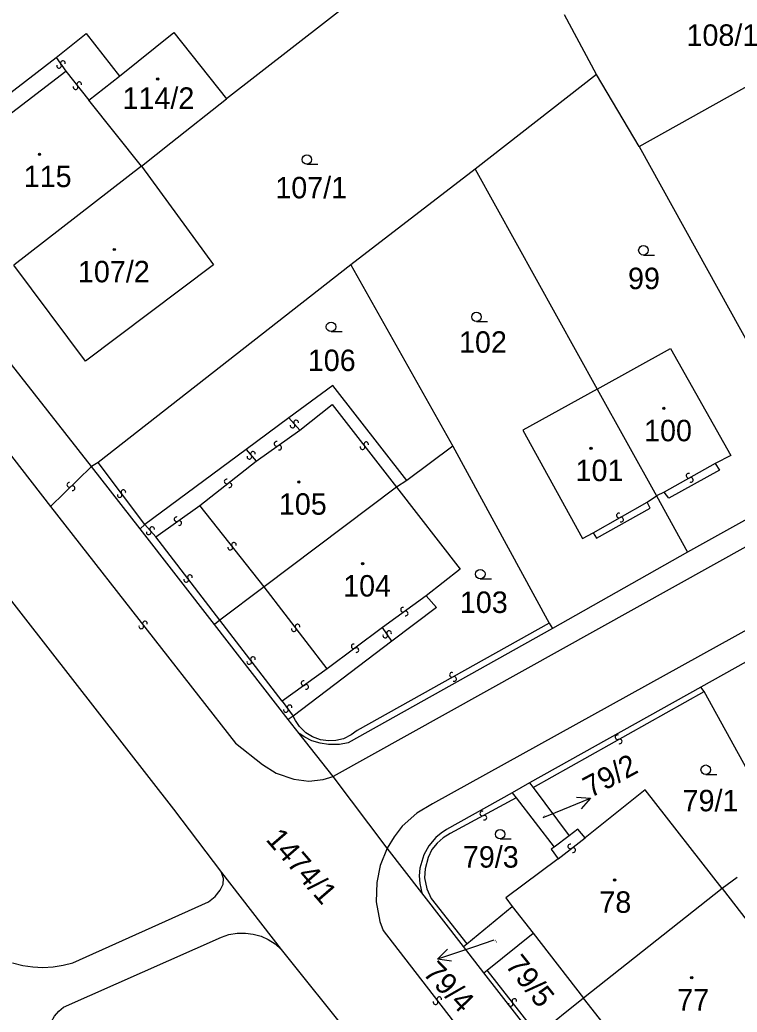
# Model space of a CAD drawing. Extents: x -600391 to -599491, y -1160176 to -1159402.
# Drawn here: x -600331.1 to -600274.3, y -1159991 to -1159912.4 of the extents above; entities that cross this region are included whole.
import ezdxf

# ---------------------------------------------------------------- set-up
doc = ezdxf.new("R2010")
doc.units = 0
for name, color, linetype in [('Level 1', 7, 'Continuous'), ('Level 13', 7, 'Continuous'), ('Level 3', 7, 'Continuous'), ('Level 4', 7, 'Continuous'), ('Level 5', 7, 'Continuous'), ('Level 57', 7, 'Continuous')]:
    doc.layers.add(name, color=color, linetype=linetype)

msp = doc.modelspace()

# ---------------------------------------------------------------- linework, layer by layer
at = {"layer": 'Level 1'}
for points in [[(-600376.7, -1159900.77), (-600365.93, -1159914.53), (-600350.97, -1159933.8), (-600318.93, -1159974.9), (-600315.13, -1159979.92)], [(-600293.45, -1159902.08), (-600314.74, -1159918.62)], [(-600285.41, -1159916.7), (-600287.96, -1159911.98)], [(-600328.23, -1159915.36), (-600325.84, -1159913.45), (-600323.21, -1159916.82)], [(-600323.21, -1159916.82), (-600318.91, -1159913.37), (-600314.74, -1159918.62)], [(-600282.04, -1159922.4), (-600265.99, -1159913.45)], [(-600341.92, -1159925.88), (-600328.23, -1159915.36)], [(-600325.64, -1159918.73), (-600323.21, -1159916.82)], [(-600285.41, -1159916.7), (-600295.04, -1159924.21)], [(-600282.04, -1159922.4), (-600285.41, -1159916.7)], [(-600321.47, -1159923.97), (-600319.15, -1159922.12), (-600314.74, -1159918.62)], [(-600321.47, -1159923.97), (-600325.64, -1159918.73)], [(-600282.04, -1159922.4), (-600267.75, -1159948.2)], [(-600321.47, -1159923.97), (-600331.59, -1159931.8)], [(-600321.47, -1159923.97), (-600315.76, -1159931.77), (-600325.9, -1159939.4), (-600331.59, -1159931.8)], [(-600295.04, -1159924.21), (-600304.87, -1159931.78)], [(-600295.04, -1159924.21), (-600285.36, -1159941.63)], [(-600304.87, -1159931.78), (-600324.9, -1159947.44)], [(-600304.87, -1159931.78), (-600296.8, -1159946.15)], [(-600325.43, -1159947.74), (-600335.56, -1159934.9)], [(-600285.36, -1159941.63), (-600279.55, -1159938.41), (-600274.77, -1159946.89), (-600276, -1159947.5)], [(-600300.43, -1159948.87), (-600306.3, -1159941.32), (-600309.79, -1159943.89)], [(-600285.36, -1159941.63), (-600291.26, -1159944.88), (-600286.53, -1159953.44), (-600285.69, -1159953)], [(-600285.36, -1159941.63), (-600280.65, -1159950.08)], [(-600309.79, -1159943.89), (-600313.18, -1159946.39)], [(-600296.8, -1159946.15), (-600300.43, -1159948.87)], [(-600296.8, -1159946.15), (-600289.16, -1159960.16)], [(-600313.18, -1159946.39), (-600321.21, -1159952.35)], [(-600324.9, -1159947.44), (-600325.43, -1159947.74)], [(-600276, -1159947.5), (-600275.66, -1159948.04), (-600279.69, -1159950.26), (-600280.06, -1159949.79)], [(-600321.58, -1159952.68), (-600325.43, -1159947.74)], [(-600300.43, -1159948.87), (-600301.27, -1159949.38)], [(-600267.56, -1159948.62), (-600278.2, -1159954.54)], [(-600301.27, -1159949.38), (-600311.75, -1159957.29)], [(-600301.27, -1159949.38), (-600296.21, -1159955.87), (-600298.92, -1159957.98)], [(-600281.41, -1159950.58), (-600280.65, -1159950.08)], [(-600280.06, -1159949.79), (-600280.65, -1159950.08)], [(-600280.65, -1159950.08), (-600278.2, -1159954.54)], [(-600285.69, -1159953), (-600285.42, -1159953.43), (-600281.15, -1159951.04), (-600281.41, -1159950.58)], [(-600321.21, -1159952.35), (-600321.58, -1159952.68)], [(-600315.69, -1159960.26), (-600321.58, -1159952.68)], [(-600278.2, -1159954.54), (-600288.91, -1159960.57)], [(-600311.75, -1159957.29), (-600315.25, -1159959.91)], [(-600298.92, -1159957.98), (-600298.1, -1159958.92), (-600301.63, -1159961.58)], [(-600266.6, -1159959.35), (-600277.15, -1159965.23)], [(-600315.25, -1159959.91), (-600315.69, -1159960.26)], [(-600309.85, -1159967.8), (-600315.69, -1159960.26)], [(-600289.16, -1159960.16), (-600288.91, -1159960.57)], [(-600288.91, -1159960.57), (-600305.08, -1159969.64), (-600305.77, -1159969.77), (-600306.65, -1159969.78), (-600307.32, -1159969.67), (-600307.96, -1159969.47), (-600308.52, -1159969.19), (-600308.97, -1159968.91)], [(-600301.63, -1159961.58), (-600309.44, -1159967.52)], [(-600277.15, -1159965.23), (-600290.71, -1159972.81)], [(-600276.88, -1159965.56), (-600277.15, -1159965.23)], [(-600270.44, -1159977.27), (-600276.88, -1159965.56)], [(-600309.44, -1159967.52), (-600309.85, -1159967.8)], [(-600308.97, -1159968.91), (-600309.85, -1159967.8)], [(-600306.27, -1159972.31), (-600308.97, -1159968.91)], [(-600301.99, -1159977.97), (-600306.27, -1159972.31)], [(-600290.71, -1159972.81), (-600292.09, -1159973.59)], [(-600290.71, -1159972.81), (-600290.44, -1159973.17)], [(-600292.09, -1159973.59), (-600297.3, -1159976.5), (-600297.73, -1159976.78), (-600298.14, -1159977.14), (-600298.69, -1159977.79), (-600299.09, -1159978.51), (-600299.4, -1159979.57), (-600299.46, -1159980.18), (-600299.42, -1159980.78), (-600299.26, -1159981.51)], [(-600292.09, -1159973.59), (-600291.77, -1159974)], [(-600290.44, -1159973.17), (-600287.57, -1159977)], [(-600275.45, -1159981.17), (-600281.56, -1159973.37), (-600286.32, -1159977.15)], [(-600291.77, -1159974), (-600288.78, -1159977.89)], [(-600286.32, -1159977.15), (-600286.88, -1159976.48), (-600287.57, -1159977)], [(-600287.57, -1159977), (-600288.78, -1159977.89)], [(-600299.26, -1159981.51), (-600301.99, -1159977.97)], [(-600288.78, -1159977.89), (-600289.01, -1159978.06), (-600288.44, -1159978.83)], [(-600288.44, -1159978.83), (-600292.61, -1159981.92), (-600292.09, -1159982.6)], [(-600331.69, -1159987.07), (-600330.88, -1159987.27), (-600330.08, -1159987.39), (-600329.28, -1159987.43), (-600328.46, -1159987.38), (-600327.67, -1159987.26), (-600326.9, -1159987.05), (-600316.16, -1159982.24), (-600315.62, -1159981.82), (-600315.23, -1159981.31), (-600315.01, -1159980.83), (-600314.98, -1159980.38), (-600315.13, -1159979.92)], [(-600315.13, -1159979.92), (-600310.39, -1159986)], [(-600274.26, -1159980.3), (-600275.45, -1159981.17)], [(-600295.95, -1159985.77), (-600299.26, -1159981.51)], [(-600275.45, -1159981.17), (-600286.44, -1159989.86)], [(-600295.7, -1159985.56), (-600292.09, -1159982.6)], [(-600292.09, -1159982.6), (-600290.44, -1159984.72)], [(-600311.92, -1160021.96), (-600308.61, -1160019.44), (-600328.17, -1159994.12), (-600328.61, -1159993.28), (-600328.73, -1159992.76), (-600328.71, -1159992.2), (-600328.59, -1159991.72), (-600328.36, -1159991.28), (-600328.03, -1159990.89), (-600327.64, -1159990.58), (-600315.13, -1159985.03), (-600314.54, -1159984.82), (-600313.88, -1159984.7), (-600313.24, -1159984.7), (-600312.61, -1159984.79), (-600311.99, -1159984.96), (-600311.43, -1159985.22), (-600310.87, -1159985.57), (-600310.39, -1159986)], [(-600294.07, -1159987.65), (-600290.44, -1159984.72)], [(-600290.44, -1159984.72), (-600286.44, -1159989.86)], [(-600310.39, -1159986), (-600304.77, -1159993.04), (-600288.6, -1160013.74), (-600276.31, -1160029.51), (-600258.7, -1160052.27), (-600242.9, -1160072.54)], [(-600295.95, -1159985.77), (-600295.7, -1159985.56)], [(-600294.33, -1159987.86), (-600295.95, -1159985.77)], [(-600294.33, -1159987.86), (-600294.07, -1159987.65)], [(-600290.33, -1159993.01), (-600294.33, -1159987.86)], [(-600286.44, -1159989.86), (-600290.07, -1159992.76)]]:
    msp.add_lwpolyline(points, dxfattribs=at)
at = {"layer": 'Level 13'}
for centre, start, end in [((-600328.001, -1159916.006), 162.54371, 35.13371), ((-600327.699, -1159915.795), 342.75816, 214.85616), ((-600326.695, -1159917.694), 165.66587, 38.25587), ((-600326.405, -1159917.466), 345.88032, 217.97832), ((-600309.499, -1159944.501), 168.42688, 41.01688), ((-600309.22, -1159944.26), 348.64134, 220.73933), ((-600310.766, -1159945.949), 72.86326, 304.96125), ((-600310.554, -1159946.25), 252.6488, 125.2388), ((-600303.956, -1159946.212), 164.95445, 37.54445), ((-600303.663, -1159945.988), 345.16891, 217.2669), ((-600312.921, -1159946.979), 167.55818, 40.14818), ((-600312.638, -1159946.742), 347.77264, 219.87064), ((-600278.12, -1159948.479), 66.58299, 299.17299), ((-600327.188, -1159949.207), 81.83894, 313.93693), ((-600326.932, -1159949.472), 261.62448, 134.21448), ((-600314.723, -1159948.934), 75.57532, 307.67332), ((-600314.497, -1159949.225), 255.36086, 127.95086), ((-600277.941, -1159948.801), 246.79744, 118.89544), ((-600323.198, -1159950.009), 164.2986, 36.3966), ((-600322.902, -1159949.79), 344.08415, 216.67415), ((-600283.639, -1159951.629), 66.85744, 298.95544), ((-600318.686, -1159951.929), 72.95711, 305.05511), ((-600318.474, -1159952.23), 252.74265, 125.33265), ((-600283.46, -1159951.951), 246.64299, 119.23299), ((-600320.898, -1159952.963), 169.61731, 41.71531), ((-600320.623, -1159952.717), 349.40285, 221.99285), ((-600314.145, -1159953.947), 345.43692, 218.02692), ((-600314.436, -1159954.173), 165.65138, 37.74937), ((-600317.634, -1159956.508), 344.77313, 217.36313), ((-600317.927, -1159956.731), 164.98759, 37.08558), ((-600300.748, -1159959.091), 73.38322, 305.97322), ((-600300.532, -1159959.39), 253.59768, 125.69568), ((-600321.485, -1159960.413), 165.21274, 37.80274), ((-600321.194, -1159960.188), 345.42719, 217.52519), ((-600309.104, -1159960.418), 344.81223, 217.40223), ((-600309.397, -1159960.641), 165.02669, 37.12469), ((-600302.154, -1159961.142), 161.42851, 33.52651), ((-600301.847, -1159960.938), 341.21406, 213.80406), ((-600304.659, -1159961.992), 73.83977, 306.42977), ((-600304.441, -1159962.289), 254.05423, 126.15223), ((-600312.927, -1159963.231), 164.90686, 37.00486), ((-600312.634, -1159963.009), 344.6924, 217.2824), ((-600296.869, -1159964.249), 66.32456, 298.91456), ((-600308.637, -1159964.91), 72.98418, 305.57418), ((-600296.692, -1159964.572), 246.53901, 118.63701), ((-600308.423, -1159965.211), 253.19863, 125.29663), ((-600310.029, -1159967.039), 163.55919, 36.14919), ((-600309.731, -1159966.822), 343.77364, 215.87164), ((-600283.749, -1159969.198), 66.67429, 298.77228), ((-600283.571, -1159969.521), 246.45983, 119.04983), ((-600294.466, -1159975.237), 65.40674, 297.99674), ((-600294.294, -1159975.563), 245.6212, 117.7192), ((-600287.493, -1159977.844), 75.7679, 307.86589), ((-600287.266, -1159978.135), 255.55344, 128.14344), ((-600298.166, -1159990.172), 164.86568, 37.45568), ((-600297.873, -1159989.949), 345.08013, 217.17813), ((-600291.925, -1159990.087), 345.21137, 217.80137), ((-600292.216, -1159990.312), 165.42582, 37.52382)]:
    msp.add_arc(centre, 0.184, start, end, dxfattribs=at)
at = {"layer": 'Level 3'}
for points in [[(-600373.58, -1159893), (-600328.68, -1159950.93)], [(-600328.23, -1159915.36), (-600327.47, -1159916.43)], [(-600337.48, -1159924.08), (-600327.47, -1159916.43)], [(-600327.47, -1159916.43), (-600325.64, -1159918.73)], [(-600219.39, -1159923.97), (-600306.27, -1159972.31)], [(-600216.41, -1159929.12), (-600298.42, -1159974.47), (-600299.65, -1159975.2), (-600300.8, -1159976.25), (-600301.45, -1159977.07), (-600301.99, -1159977.97)], [(-600308.93, -1159944.87), (-600306.35, -1159942.83), (-600301.27, -1159949.38)], [(-600309.79, -1159943.89), (-600308.93, -1159944.87)], [(-600312.38, -1159947.33), (-600308.93, -1159944.87)], [(-600313.18, -1159946.39), (-600312.38, -1159947.33)], [(-600321.21, -1159952.35), (-600324.9, -1159947.44)], [(-600316.84, -1159950.84), (-600312.38, -1159947.33)], [(-600276, -1159947.5), (-600280.06, -1159949.79)], [(-600328.68, -1159950.93), (-600325.43, -1159947.74)], [(-600320.32, -1159953.33), (-600316.84, -1159950.84)], [(-600311.75, -1159957.29), (-600316.84, -1159950.84)], [(-600285.69, -1159953), (-600281.41, -1159950.58)], [(-600328.68, -1159950.93), (-600314.01, -1159969.67), (-600311.89, -1159971.35), (-600310.8, -1159972.05), (-600309.41, -1159972.52), (-600308.22, -1159972.66), (-600307.06, -1159972.53), (-600306.27, -1159972.31)], [(-600320.32, -1159953.33), (-600321.21, -1159952.35)], [(-600315.25, -1159959.91), (-600320.32, -1159953.33)], [(-600306.75, -1159963.77), (-600311.75, -1159957.29)], [(-600298.92, -1159957.98), (-600302.36, -1159960.5)], [(-600310.31, -1159966.34), (-600315.25, -1159959.91)], [(-600289.16, -1159960.16), (-600304.39, -1159968.66), (-600304.86, -1159969.01), (-600305.46, -1159969.31), (-600306.07, -1159969.45), (-600306.65, -1159969.48), (-600307.29, -1159969.39), (-600307.91, -1159969.16), (-600308.44, -1159968.84), (-600308.94, -1159968.34), (-600309.26, -1159967.88), (-600309.44, -1159967.52)], [(-600302.36, -1159960.5), (-600306.75, -1159963.77)], [(-600301.63, -1159961.58), (-600302.36, -1159960.5)], [(-600306.75, -1159963.77), (-600310.31, -1159966.34)], [(-600290.44, -1159973.17), (-600276.88, -1159965.56)], [(-600310.31, -1159966.34), (-600309.44, -1159967.52)], [(-600291.77, -1159974), (-600297, -1159976.81), (-600297.56, -1159977.17), (-600298.05, -1159977.59), (-600298.45, -1159978.09), (-600298.76, -1159978.72), (-600298.99, -1159979.63), (-600299.03, -1159980.33), (-600298.86, -1159981.21), (-600298.51, -1159981.97), (-600295.7, -1159985.56)], [(-600288.44, -1159978.83), (-600286.32, -1159977.15)], [(-600301.99, -1159977.97), (-600302.55, -1159979.34), (-600302.82, -1159980.71), (-600302.86, -1159982.24), (-600302.57, -1159983.78), (-600302.33, -1159984.49), (-600293.71, -1159995.64)], [(-600275.45, -1159981.17), (-600269.43, -1159988.96), (-600273.11, -1159991.88)], [(-600290.07, -1159992.76), (-600294.07, -1159987.65)], [(-600276.88, -1159994.84), (-600280.39, -1159997.55), (-600286.44, -1159989.86)]]:
    msp.add_lwpolyline(points, dxfattribs=at)
at = {"layer": 'Level 5'}
for p, q in [((-600308.36, -1159923.81), (-600307.485, -1159923.81)), ((-600281.7, -1159931), (-600280.825, -1159931)), ((-600294.93, -1159936.27), (-600294.055, -1159936.27)), ((-600306.45, -1159937.06), (-600305.575, -1159937.06)), ((-600294.62, -1159956.65), (-600293.745, -1159956.65)), ((-600276.76, -1159972.14), (-600275.885, -1159972.14)), ((-600293.05, -1159977.25), (-600292.175, -1159977.25))]:
    msp.add_line(p, q, dxfattribs=at)
for centre, radius in [((-600320.18, -1159917.06), 0.09), ((-600320.18, -1159917.06), 0.0521), ((-600329.55, -1159923.02), 0.09), ((-600329.55, -1159923.02), 0.0521), ((-600308.36, -1159923.435), 0.375), ((-600281.7, -1159930.625), 0.375), ((-600323.63, -1159930.56), 0.09), ((-600323.63, -1159930.56), 0.0521), ((-600294.93, -1159935.895), 0.375), ((-600306.45, -1159936.685), 0.375), ((-600280.08, -1159943.15), 0.09), ((-600280.08, -1159943.15), 0.0521), ((-600285.84, -1159946.31), 0.09), ((-600285.84, -1159946.31), 0.0521), ((-600309, -1159948.97), 0.09), ((-600309, -1159948.97), 0.0521), ((-600303.95, -1159955.45), 0.09), ((-600303.95, -1159955.45), 0.0521), ((-600294.62, -1159956.275), 0.375), ((-600276.76, -1159971.765), 0.375), ((-600293.05, -1159976.875), 0.375), ((-600283.98, -1159980.5), 0.09), ((-600283.98, -1159980.5), 0.0521), ((-600277.87, -1159988.24), 0.09), ((-600277.87, -1159988.24), 0.0521)]:
    msp.add_circle(centre, radius, dxfattribs=at)
at = {"layer": 'Level 57'}
for p, q in [((-600288.671, -1159975.154), (-600285.89, -1159974.028)), ((-600289.65, -1159975.55), (-600288.671, -1159975.154)), ((-600293.54, -1159985.28), (-600295.17, -1159985.82)), ((-600295.17, -1159985.82), (-600298.018, -1159986.763))]:
    msp.add_line(p, q, dxfattribs=at)
for points in [[(-600287.005, -1159973.94), (-600285.89, -1159974.028), (-600286.63, -1159974.867)], [(-600296.912, -1159986.923), (-600298.018, -1159986.763), (-600297.226, -1159985.974)]]:
    msp.add_lwpolyline(points, dxfattribs=at)

# ---------------------------------------------------------------- texts
at = {"layer": 'Level 4'}
for s, p in [('108/1', (-600278.282, -1159914.43)), ('114/2', (-600322.97, -1159919.42)), ('115', (-600330.801, -1159925.62)), ('107/1', (-600310.863, -1159926.51)), ('107/2', (-600326.505, -1159933.16)), ('99', (-600282.916, -1159933.7)), ('102', (-600296.306, -1159938.74)), ('106', (-600308.291, -1159940.19)), ('100', (-600281.644, -1159945.75)), ('101', (-600287.074, -1159948.91)), ('105', (-600310.582, -1159951.57)), ('104', (-600305.491, -1159958.05)), ('103', (-600296.238, -1159959.35)), ('79/1', (-600278.588, -1159975.06)), ('79/3', (-600296.002, -1159979.52)), ('78', (-600285.188, -1159983.1)), ('77', (-600279.015, -1159990.84))]:
    msp.add_text(s, height=1.7, dxfattribs=at).set_placement(p)
for s, height, rotation, p in [('79/2', 0.1, 28.19682, (-600289.65, -1159975.55)), ('1474/1', 1.7, 310.95792, (-600311.68, -1159977.32)), ('79/4', 0.1, 313.88607, (-600293.54, -1159985.28)), ('79/5', 1.7, 308.63394, (-600292.705, -1159987.284))]:
    msp.add_text(s, height=height, rotation=rotation, dxfattribs=at).set_placement(p)
at = {"layer": 'Level 57'}
for s, rotation, p in [('79/2', 28.19682, (-600285.89, -1159974.028)), ('79/4', 313.88607, (-600299.244, -1159987.941))]:
    msp.add_text(s, height=1.7, rotation=rotation, dxfattribs=at).set_placement(p)

doc.saveas('drawing.dxf')
